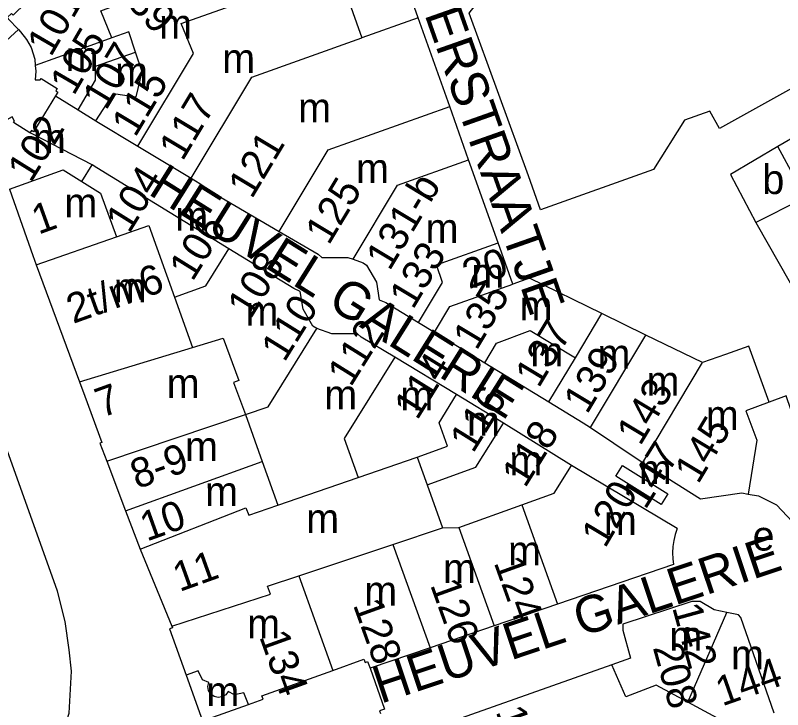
# Model space of a CAD drawing. Extents: x 160673 to 161924, y 382258 to 384145.
# Drawn here: x 161359.3 to 161463.2, y 383327.4 to 383421.3 of the extents above; entities that cross this region are included whole.
import ezdxf

# ---------------------------------------------------------------- set-up
doc = ezdxf.new("R2010")
doc.units = 0
for name, color, linetype in [('BLT_Basislijn', 7, 'Continuous'), ('BLT_Bebouwing', 7, 'Continuous'), ('BLT_Centroide', 7, 'Continuous'), ('BLT_Huisnummer', 7, 'Continuous'), ('BLT_Huisnummer_reeks', 7, 'Continuous'), ('BLT_Onderdoorgang_en_onderverdeling', 7, 'Continuous'), ('BLT_Onderverdeling_panden', 7, 'Continuous'), ('BLT_Straatnaam', 7, 'Continuous')]:
    doc.layers.add(name, color=color, linetype=linetype)

msp = doc.modelspace()

# ---------------------------------------------------------------- linework, layer by layer
at = {"layer": 'BLT_Basislijn'}
for p, q in [((161359.67, 383419.42), (161357.46, 383417.38)), ((161476.12, 383411.66), (161462.5, 383403.58))]:
    msp.add_line(p, q, dxfattribs=at)
msp.add_lwpolyline([(161354.32, 383311.3), (161355.34, 383312.31), (161359.55, 383315.09), (161362.49, 383317.94), (161364.1, 383320.41), (161365.06, 383322.25), (161366.56, 383326.94), (161366.85, 383332.59), (161366.55, 383335.51), (161366, 383339.32), (161364.95, 383343.45), (161344.75, 383399.92)], dxfattribs=at)
at = {"layer": 'BLT_Bebouwing'}
for p, q in [((161418.07, 383409), (161413.8, 383421)), ((161420.63, 383401.8), (161418.07, 383409)), ((161453.29, 383408.36), (161449.86, 383407.14)), ((161424.64, 383390.55), (161420.63, 383401.8)), ((161459.52, 383393.32), (161464.15, 383385.17)), ((161426.62, 383384.99), (161424.64, 383390.55)), ((161362.09, 383387.57), (161367.94, 383371.74)), ((161444.63, 383378.09), (161438.69, 383380.98)), ((161452.3, 383374.35), (161444.63, 383378.09)), ((161455.43, 383375.47), (161452.3, 383374.35)), ((161374.17, 383354.32), (161376.15, 383349.11)), ((161376.15, 383349.11), (161380.44, 383338.7))]:
    msp.add_line(p, q, dxfattribs=at)
for points in [[(161428.73, 383399.62), (161420.71, 383421.64), (161425.14, 383427.34), (161424.78, 383427.61), (161427.99, 383431.78), (161427.23, 383433.15), (161438.17, 383439.33)], [(161367.45, 383429.66), (161358.98, 383421.38), (161358.74, 383421.59), (161358.13, 383421.03), (161358.29, 383420.86), (161359.67, 383419.42)], [(161413.8, 383421), (161411.94, 383426.23), (161411.23, 383428.23)], [(161480.67, 383420.53), (161454.6, 383406.02), (161453.29, 383408.36)], [(161359.67, 383419.42), (161359.95, 383419.13), (161360.79, 383418.08)], [(161360.79, 383418.08), (161361.38, 383416.98), (161361.89, 383415.41), (161361.96, 383414.54)], [(161361.96, 383414.54), (161362.02, 383413.8), (161361.92, 383412.62), (161362.61, 383412.6), (161362.74, 383412.81), (161364.93, 383411.46), (161364.74, 383411.15), (161365.03, 383410.97), (161364.71, 383410.44)], [(161364.71, 383410.44), (161361.72, 383405.6), (161361.44, 383405.78), (161361.24, 383405.46)], [(161361.24, 383405.46), (161359.03, 383406.83), (161359.15, 383407.02), (161358.83, 383407.62), (161357.8, 383407.01), (161357.13, 383406.77)], [(161449.86, 383407.14), (161445.65, 383400.49), (161430.35, 383395.03), (161428.73, 383399.62)], [(161462.5, 383403.58), (161456.11, 383399.79), (161459.52, 383393.32)], [(161466.2, 383396.69), (161464.88, 383399.17), (161462.5, 383403.58)], [(161358.45, 383397.82), (161361.62, 383388.87), (161362.09, 383387.57)], [(161438.69, 383380.98), (161428.86, 383385.77), (161426.62, 383384.99)], [(161461.32, 383369), (161458.57, 383376.59), (161455.43, 383375.47)], [(161367.94, 383371.74), (161368.65, 383369.83), (161370.96, 383363.55), (161370.69, 383363.44), (161371.63, 383361.03)], [(161475.02, 383360.72), (161466.96, 383364.53), (161465.63, 383364.06), (161463.61, 383369.84), (161461.32, 383369)], [(161371.63, 383361.03), (161374.17, 383354.32)], [(161380.44, 383338.7), (161380.52, 383338.48), (161380.15, 383338.35), (161382.39, 383332.07)], [(161402.23, 383332.71), (161406.46, 383334.22), (161406.62, 383333.77), (161406.96, 383333.89), (161407.28, 383333)], [(161407.28, 383333), (161409.25, 383327.48), (161408.55, 383327.24), (161408.68, 383326.86)], [(161382.39, 383332.07), (161384.59, 383325.89), (161390.81, 383328.1)], [(161390.81, 383328.1), (161392.81, 383328.81), (161392.64, 383329.27), (161402.23, 383332.71)]]:
    msp.add_lwpolyline(points, dxfattribs=at)
at = {"layer": 'BLT_Onderdoorgang_en_onderverdeling'}
msp.add_lwpolyline([(161390.81, 383328.1), (161390.2, 383329.66), (161388.93, 383329.41), (161388.07, 383329.83), (161387.74, 383329.4), (161387.23, 383329.11), (161386.7, 383329.04), (161386.16, 383329.17), (161385.73, 383329.48), (161385.42, 383329.98), (161385.33, 383330.53), (161385.45, 383331.07), (161384.6, 383331.45), (161384.01, 383332.65), (161382.39, 383332.07)], dxfattribs=at)
at = {"layer": 'BLT_Onderverdeling_panden'}
for p, q in [((161403.6, 383425.51), (161406.17, 383418.29)), ((161413.8, 383421), (161406.17, 383418.29)), ((161372.33, 383418.28), (161367.97, 383416.71)), ((161367.97, 383416.71), (161361.96, 383414.54)), ((161364.71, 383410.44), (161367.75, 383408.56)), ((161367.75, 383408.56), (161370.14, 383407.08)), ((161375.84, 383403.65), (161383.07, 383399.31)), ((161368.28, 383398.88), (161369.68, 383401.13)), ((161466.2, 383396.68), (161459.52, 383393.32)), ((161362.09, 383387.57), (161372.95, 383391.36)), ((161380.79, 383383.22), (161383.24, 383376.38)), ((161435.1, 383375.01), (161438.69, 383380.98)), ((161413.85, 383379.78), (161415.99, 383378.48)), ((161415.99, 383378.48), (161422.82, 383374.32)), ((161437.12, 383365.58), (161444.63, 383378.09)), ((161367.94, 383371.74), (161383.24, 383376.38)), ((161419.01, 383370.03), (161410.62, 383375.11)), ((161431.51, 383369.03), (161435.1, 383375.01)), ((161422.82, 383374.32), (161431.51, 383369.03)), ((161444.2, 383360.85), (161452.3, 383374.35)), ((161390.42, 383367.35), (161393.49, 383368.39)), ((161461.32, 383369), (161458.17, 383367.85)), ((161371.63, 383361.03), (161390.42, 383367.35)), ((161390.42, 383367.35), (161392.7, 383360.99)), ((161434.56, 383360.43), (161425.34, 383366.18)), ((161374.17, 383354.32), (161392.7, 383360.99)), ((161392.7, 383360.99), (161394.82, 383355.06)), ((161405.67, 383358.81), (161413.68, 383361.58)), ((161413.68, 383361.58), (161415.02, 383357.83)), ((161448.89, 383351.9), (161434.56, 383360.43)), ((161394.82, 383355.06), (161405.67, 383358.81)), ((161415.02, 383357.83), (161417.11, 383351.98)), ((161419.31, 383352.04), (161427.83, 383355.11)), ((161427.83, 383355.11), (161432.67, 383341.67)), ((161410.38, 383349.75), (161417.11, 383351.98)), ((161417.11, 383351.98), (161419.31, 383352.04)), ((161419.31, 383352.04), (161424.1, 383338.74)), ((161397.62, 383345.52), (161410.38, 383349.75)), ((161410.38, 383349.75), (161415.41, 383335.78)), ((161448.38, 383347.03), (161432.67, 383341.67)), ((161397.62, 383345.52), (161402.23, 383332.71)), ((161432.67, 383341.67), (161424.1, 383338.74)), ((161450.3, 383328.41), (161455.6, 383340.56)), ((161424.1, 383338.74), (161415.41, 383335.78)), ((161415.41, 383335.78), (161407.28, 383333)), ((161440.02, 383333.44), (161410.43, 383323.03)), ((161456.58, 383325.03), (161450.3, 383328.41))]:
    msp.add_line(p, q, dxfattribs=at)
for points in [[(161375.84, 383403.65), (161383.36, 383416.18), (161381.72, 383420.23), (161402.8, 383427.74)], [(161372.33, 383418.28), (161370.84, 383421.95), (161373.64, 383422.99), (161373.88, 383423.08)], [(161375.54, 383416.36), (161374.61, 383419.1), (161372.33, 383418.28)], [(161383.07, 383399.31), (161391.28, 383412.99), (161406.17, 383418.29)], [(161367.75, 383408.56), (161370.09, 383412.59), (161370.11, 383414.46), (161375.54, 383416.36)], [(161370.14, 383407.08), (161372.54, 383410.75), (161375.62, 383410.3), (161376.43, 383413.7), (161375.54, 383416.36)], [(161395, 383392.11), (161401.63, 383403.15), (161418.07, 383409)], [(161370.14, 383407.08), (161370.3, 383406.97), (161375.84, 383403.65)], [(161369.68, 383401.13), (161361.53, 383405.29), (161361.24, 383405.46)], [(161404.98, 383388.34), (161411.01, 383398.38), (161420.63, 383401.8)], [(161358.45, 383397.82), (161365.75, 383400.45), (161368.28, 383398.88)], [(161388.16, 383389.77), (161370.3, 383400.72), (161369.68, 383401.13)], [(161383.07, 383399.31), (161384.24, 383398.61), (161386.35, 383397.14), (161395, 383392.11)], [(161368.28, 383398.88), (161370.81, 383397.3), (161372.95, 383391.36)], [(161372.95, 383391.36), (161377.32, 383392.89), (161380.79, 383383.22)], [(161395, 383392.11), (161400.28, 383389.04), (161400.76, 383388.56), (161404.27, 383388.59), (161404.98, 383388.34)], [(161413.85, 383379.78), (161417.1, 383385.21), (161416.26, 383387.57), (161424.64, 383390.55)], [(161380.79, 383383.22), (161385.03, 383384.75), (161388.16, 383389.77)], [(161400.06, 383378.96), (161399.55, 383379.3), (161398.22, 383381.6), (161397.84, 383383.99), (161396.95, 383384.38), (161388.16, 383389.77)], [(161404.98, 383388.34), (161406.34, 383387.86), (161406.82, 383387.54), (161408.15, 383385.24), (161408.54, 383382.86), (161409.43, 383382.47), (161413.85, 383379.78)], [(161415.99, 383378.48), (161418.07, 383381.94), (161426.62, 383384.99)], [(161393.49, 383368.39), (161400.06, 383378.96)], [(161410.62, 383375.11), (161406.08, 383377.78), (161405.6, 383378.26), (161402.09, 383378.24), (161400.06, 383378.96)], [(161422.82, 383374.32), (161424.41, 383376.97), (161428.98, 383378.68), (161435.1, 383375.01)], [(161383.24, 383376.38), (161387.4, 383377.64), (161389.54, 383371.95), (161388.8, 383371.67), (161390.42, 383367.35)], [(161410.62, 383375.11), (161403.77, 383364.1), (161405.67, 383358.81)], [(161413.68, 383361.58), (161417.78, 383363.05), (161416.64, 383366.22), (161419.01, 383370.03)], [(161425.34, 383366.18), (161419.01, 383370.03)], [(161431.51, 383369.03), (161436.14, 383366.22), (161437.12, 383365.58)], [(161458.17, 383367.85), (161459.65, 383363.86), (161458.49, 383356.57)], [(161415.02, 383357.83), (161421.62, 383360.21), (161425.34, 383366.18)], [(161437.12, 383365.58), (161443.45, 383361.32), (161444.2, 383360.85)], [(161427.83, 383355.11), (161432.23, 383356.69), (161434.56, 383360.43)], [(161444.2, 383360.85), (161452.01, 383355.9), (161457.62, 383356.72), (161458.49, 383356.57)], [(161458.49, 383356.57), (161459.88, 383356.33), (161462.33, 383355.13), (161464.49, 383352.82)], [(161376.15, 383349.11), (161390.48, 383354.71), (161390.87, 383353.7), (161394.82, 383355.06)], [(161448.89, 383351.9), (161448.61, 383351.11), (161448.4, 383350.3), (161448.28, 383349.47), (161448.24, 383348.63), (161448.27, 383347.79), (161448.38, 383347.03)], [(161380.44, 383338.7), (161393.79, 383343.01), (161393.4, 383344.12), (161397.62, 383345.52)], [(161455.6, 383340.56), (161453.89, 383340.91), (161451.98, 383342.02), (161450.86, 383342.02), (161441.52, 383338.94), (161441.52, 383338.14), (161442.57, 383334.34), (161440.02, 383333.44)], [(161462.01, 383326.94), (161457.5, 383339.86), (161457.18, 383340.23), (161455.6, 383340.56)], [(161450.3, 383328.41), (161446.02, 383330.71), (161441.94, 383329.11), (161440.02, 383333.44)]]:
    msp.add_lwpolyline(points, dxfattribs=at)
msp.add_lwpolyline([(161440.57, 383358.97), (161441.48, 383360.43), (161447.59, 383356.61), (161446.68, 383355.16)], close=True, dxfattribs=at)

# ---------------------------------------------------------------- texts
at = {"layer": 'BLT_Centroide'}
for s, p in [('m', (161378.73, 383418.19)), ('m', (161366.06, 383413.81)), ('m', (161387.27, 383413.53)), ('m', (161372.77, 383411.72)), ('m', (161397.55, 383406.85)), ('m', (161361.63, 383402.72)), ('m', (161405.38, 383398.66)), ('b', (161460.4, 383397.17)), ('m', (161365.9, 383394)), ('m', (161380.91, 383392.19)), ('m', (161414.81, 383390.55)), ('m', (161420.99, 383384.5)), ('m', (161372.59, 383382.52)), ('m', (161427.53, 383380.06)), ('m', (161390.42, 383379.34)), ('m', (161428.99, 383373.84)), ('m', (161438.08, 383373.55)), ('m', (161379.75, 383369.56)), ('m', (161444.72, 383369.88)), ('m', (161401.09, 383368.02)), ('m', (161411.39, 383367.91)), ('m', (161452.75, 383365.25)), ('m', (161420.42, 383364.47)), ('m', (161382.23, 383361.03)), ('m', (161426.16, 383359.12)), ('m', (161443.68, 383357.91)), ('m', (161384.95, 383354.94)), ('m', (161398.64, 383351.28)), ('m', (161438.95, 383351.03)), ('e', (161459.08, 383348.92)), ('m', (161425.98, 383346.91)), ('m', (161417.16, 383344.53)), ('m', (161406.5, 383341.48)), ('m', (161390.65, 383337.03)), ('m', (161447.81, 383335.38)), ('m', (161456.16, 383332.84)), ('m', (161385.12, 383327.87))]:
    msp.add_text(s, height=4, dxfattribs=at).set_placement(p)
at = {"layer": 'BLT_Huisnummer'}
for s, rotation, p in [('1', 19.7836, (161362.38, 383391.65)), ('7', 19.7819, (161370.97, 383366.87)), ('10', 19.7819, (161377.05, 383350.12)), ('11', 19.7822, (161381.49, 383343.3))]:
    msp.add_text(s, height=4, rotation=rotation, dxfattribs=at).set_placement(p)
at = {"layer": 'BLT_Huisnummer_reeks'}
for s, rotation, p in [('29t/m39', 314.0269, (161364.95, 383432.47)), ('101-103', 59.8452, (161364.07, 383415.6)), ('105', 59.8452, (161367.18, 383410.35)), ('107', 59.0134, (161371.54, 383408.36)), ('115', 59.0134, (161375.49, 383404.72)), ('117', 59.0098, (161381.89, 383401.49)), ('102', 58.0954, (161361.35, 383398.55)), ('121', 59.0095, (161391.27, 383396.38)), ('104', 58.1045, (161374.67, 383391.7)), ('125', 59.0095, (161401.7, 383390.12)), ('131-b', 59.0083, (161409.92, 383386.64)), ('106', 58.1045, (161383.24, 383385.21)), ('133', 59.0083, (161413.1, 383381.42)), ('108', 58.1093, (161391.11, 383380.12)), ('20', 19.5952, (161420.67, 383384.27)), ('2t/m6', 19.7819, (161367.08, 383379.58)), ('135', 59.0108, (161421.71, 383375.87)), ('110', 58.1093, (161395.69, 383374.29)), ('112', 58.1056, (161404.68, 383370.94)), ('137', 59.008, (161430.12, 383370.79)), ('114', 58.1044, (161413.67, 383366.44)), ('139', 59.0093, (161436.67, 383367.25)), ('143', 59.0138, (161443.87, 383362.97)), ('116', 58.1051, (161421.23, 383361.97)), ('145', 59.0138, (161451.71, 383357.79)), ('118', 58.105, (161428.28, 383357.27)), ('8-9', 19.7821, (161375.73, 383357.2)), ('147', 58.0069, (161444.57, 383354.34)), ('120', 59.2537, (161439.1, 383349.11)), ('124', 289.7809, (161424, 383347.31)), ('126', 289.7842, (161415.39, 383344.29)), ('128', 289.7829, (161404.94, 383341.59)), ('142', 285.4371, (161448.17, 383341.23)), ('134', 289.7829, (161392.25, 383337.3)), ('208', 285.4371, (161445.55, 383335.82)), ('144', 19.3854, (161454.97, 383327.82)), ('140', 288.9812, (161424.27, 383327.15))]:
    msp.add_text(s, height=4, rotation=rotation, dxfattribs=at).set_placement(p)
at = {"layer": 'BLT_Straatnaam'}
for s, height, rotation, p in [('GENDERSTRAATJE', 4.9999, 289.3989, (161408.21, 383439.72)), ('HEUVEL GALERIE', 4.9999, 327.8937, (161377.09, 383397.23)), ('HEUVEL GALERIE', 5, 18.4616, (161408.72, 383328.16))]:
    msp.add_text(s, height=height, rotation=rotation, dxfattribs=at).set_placement(p)

doc.saveas('drawing.dxf')
